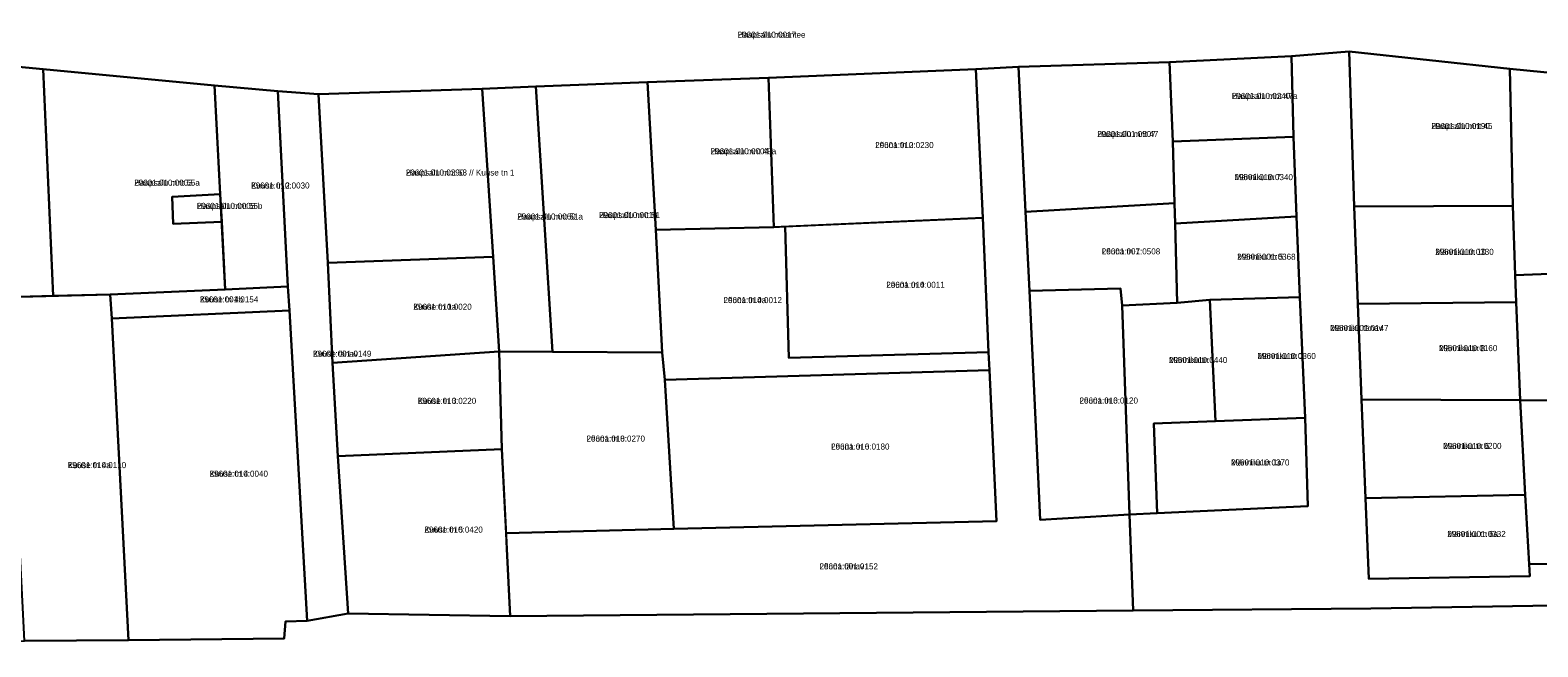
# Model space of a CAD drawing. Extents: x 518839 to 525192, y 6573164 to 6576561.
# Drawn here: x 522991.1 to 523365.3, y 6574299.5 to 6574452.7 of the extents above; entities that cross this region are included whole.
import ezdxf

# ---------------------------------------------------------------- set-up
doc = ezdxf.new("R2010")
doc.units = 0
for name, color, linetype in [('L_AADRESS', 7, 'Continuous'), ('PIIR', 7, 'Continuous'), ('TUNNUS', 7, 'Continuous')]:
    doc.layers.add(name, color=color, linetype=linetype)

msp = doc.modelspace()

# ---------------------------------------------------------------- linework, layer by layer
at = {"layer": 'PIIR'}
for points in [[(523375.25, 6574441.47), (523358.38, 6574443.13), (523318.49, 6574447.43), (523304.19, 6574446.22), (523273.88, 6574444.71), (523236.44, 6574443.56), (523225.85, 6574443.01), (523174.31, 6574440.89), (523144.32, 6574439.75), (523116.58, 6574438.68), (523103.26, 6574438.16), (523062.66, 6574436.81), (523052.55, 6574437.56), (523036.83, 6574438.96), (522994.3, 6574443.04), (522954.98, 6574446.76), (522904.74, 6574450.97), (522839.77, 6574456.33), (522694.1, 6574453.03)], [(522817.9, 6574265.68), (522818.87, 6574305.73), (522845.06, 6574303.47), (522909.55, 6574299.99), (522989.61, 6574301.01), (523015.47, 6574301.19), (523054.1, 6574301.61), (523054.47, 6574305.84), (523059.82, 6574306.01), (523069.97, 6574307.81), (523110.19, 6574307.2), (523264.85, 6574308.54), (523323.9, 6574309.05), (523389.23, 6574310.15)]]:
    msp.add_lwpolyline(points, dxfattribs=at)
for points in [[(522994.3, 6574443.04), (522996.8, 6574386.69), (522985.33, 6574386.41), (522958.36, 6574385.9), (522954.98, 6574446.76)], [(523304.72, 6574426.21), (523304.19, 6574446.22), (523318.49, 6574447.43), (523319.75, 6574408.88), (523320.68, 6574384.72), (523321.56, 6574360.96), (523322.56, 6574336.43), (523323.36, 6574316.4), (523363.35, 6574317.07), (523363.18, 6574320.07), (523388.79, 6574320.15), (523389.23, 6574310.15), (523323.9, 6574309.05), (523264.85, 6574308.54), (523264.01, 6574332.43), (523270.83, 6574332.75), (523308.28, 6574334.49), (523307.58, 6574356.42), (523306.24, 6574386.39), (523305.44, 6574406.38)], [(523273.88, 6574444.71), (523304.19, 6574446.22), (523304.72, 6574426.21), (523274.71, 6574425.02)], [(523359.17, 6574409.07), (523319.75, 6574408.88), (523318.49, 6574447.43), (523358.38, 6574443.13)], [(523036.83, 6574438.96), (523038.25, 6574411.98), (523026.31, 6574411.27), (523026.54, 6574404.64), (523038.61, 6574405.09), (523039.49, 6574388.26), (523010.94, 6574387.03), (522996.8, 6574386.69), (522994.3, 6574443.04)], [(523110.19, 6574307.2), (523109.38, 6574323.85), (523109.19, 6574327.74), (523150.83, 6574328.84), (523230.97, 6574330.77), (523229.19, 6574368.25), (523228.99, 6574372.75), (523227.53, 6574406.12), (523225.85, 6574443.01), (523236.44, 6574443.56), (523238.18, 6574407.6), (523239.13, 6574387.94), (523241.79, 6574331.1), (523264.01, 6574332.43), (523264.85, 6574308.54)], [(523174.31, 6574440.89), (523225.85, 6574443.01), (523227.53, 6574406.12), (523175.64, 6574403.81)], [(523238.18, 6574407.6), (523236.44, 6574443.56), (523273.88, 6574444.71), (523274.71, 6574425.02), (523275.14, 6574409.72)], [(523375.25, 6574441.47), (523374.88, 6574392.44), (523359.74, 6574391.88), (523359.17, 6574409.07), (523358.38, 6574443.13)], [(523399.43, 6574438.95), (523399.48, 6574434.63), (523400.69, 6574412.15), (523384.94, 6574411.42), (523386.45, 6574373.96), (523387.04, 6574360.55), (523360.93, 6574360.82), (523359.96, 6574385.13), (523359.74, 6574391.88), (523374.88, 6574392.44), (523375.25, 6574441.47)], [(523036.83, 6574438.96), (523052.55, 6574437.56), (523055.01, 6574389.05), (523039.49, 6574388.26)], [(523055.01, 6574389.05), (523052.55, 6574437.56), (523062.66, 6574436.81), (523064.93, 6574394.94), (523066.13, 6574370.09), (523067.45, 6574346.92), (523069.97, 6574307.81), (523059.82, 6574306.01), (523055.46, 6574383.09)], [(523062.66, 6574436.81), (523103.26, 6574438.16), (523105.98, 6574396.43), (523064.93, 6574394.94)], [(523105.98, 6574396.43), (523103.26, 6574438.16), (523116.58, 6574438.68), (523120.72, 6574372.82), (523107.52, 6574372.86)], [(523116.58, 6574438.68), (523144.32, 6574439.75), (523146.4, 6574403.12), (523147.99, 6574372.67), (523120.72, 6574372.82)], [(523174.31, 6574440.89), (523175.64, 6574403.81), (523146.4, 6574403.12), (523144.32, 6574439.75)], [(523275.28, 6574404.69), (523275.14, 6574409.72), (523274.71, 6574425.02), (523304.72, 6574426.21), (523305.44, 6574406.38)], [(523038.25, 6574411.98), (523038.61, 6574405.09), (523026.54, 6574404.64), (523026.31, 6574411.27)], [(523239.13, 6574387.94), (523238.18, 6574407.6), (523275.14, 6574409.72), (523275.28, 6574404.69), (523275.84, 6574384.99), (523262.14, 6574384.3), (523261.74, 6574388.5)], [(523320.68, 6574384.72), (523319.75, 6574408.88), (523359.17, 6574409.07), (523359.74, 6574391.88), (523359.96, 6574385.13)], [(523146.4, 6574403.12), (523175.64, 6574403.81), (523178.47, 6574403.94), (523179.43, 6574371.29), (523228.99, 6574372.75), (523229.19, 6574368.25), (523148.62, 6574365.88), (523147.99, 6574372.67)], [(523178.47, 6574403.94), (523227.53, 6574406.12), (523228.99, 6574372.75), (523179.43, 6574371.29)], [(523283.89, 6574385.71), (523275.84, 6574384.99), (523275.28, 6574404.69), (523305.44, 6574406.38), (523306.24, 6574386.39)], [(523064.93, 6574394.94), (523105.98, 6574396.43), (523107.52, 6574372.86), (523066.13, 6574370.09)], [(523011.36, 6574381.1), (523010.94, 6574387.03), (523039.49, 6574388.26), (523055.01, 6574389.05), (523055.46, 6574383.09)], [(522985.33, 6574386.41), (523010.94, 6574387.03), (523011.36, 6574381.1), (523015.47, 6574301.19), (522989.61, 6574301.01)], [(523239.13, 6574387.94), (523261.74, 6574388.5), (523262.14, 6574384.3), (523264.01, 6574332.43), (523241.79, 6574331.1)], [(523275.84, 6574384.99), (523283.89, 6574385.71), (523285.36, 6574355.61), (523269.99, 6574355.04), (523270.83, 6574332.75), (523264.01, 6574332.43), (523262.14, 6574384.3)], [(523285.36, 6574355.61), (523283.89, 6574385.71), (523306.24, 6574386.39), (523307.58, 6574356.42)], [(523320.68, 6574384.72), (523359.96, 6574385.13), (523360.93, 6574360.82), (523321.56, 6574360.96)], [(523011.36, 6574381.1), (523055.46, 6574383.09), (523059.82, 6574306.01), (523054.47, 6574305.84), (523054.1, 6574301.61), (523015.47, 6574301.19)], [(523066.13, 6574370.09), (523107.52, 6574372.86), (523108.16, 6574348.64), (523067.45, 6574346.92)], [(523148.62, 6574365.88), (523150.83, 6574328.84), (523109.19, 6574327.74), (523108.16, 6574348.64), (523107.52, 6574372.86), (523120.72, 6574372.82), (523147.99, 6574372.67)], [(523148.62, 6574365.88), (523229.19, 6574368.25), (523230.97, 6574330.77), (523150.83, 6574328.84)], [(523321.56, 6574360.96), (523360.93, 6574360.82), (523362.23, 6574337.28), (523322.56, 6574336.43)], [(523362.23, 6574337.28), (523360.93, 6574360.82), (523387.04, 6574360.55), (523388.79, 6574320.15), (523363.18, 6574320.07)], [(523270.83, 6574332.75), (523269.99, 6574355.04), (523285.36, 6574355.61), (523307.58, 6574356.42), (523308.28, 6574334.49)], [(523108.16, 6574348.64), (523109.38, 6574323.85), (523110.19, 6574307.2), (523069.97, 6574307.81), (523067.45, 6574346.92)], [(523322.56, 6574336.43), (523362.23, 6574337.28), (523363.18, 6574320.07), (523363.35, 6574317.07), (523323.36, 6574316.4)]]:
    msp.add_lwpolyline(points, close=True, dxfattribs=at)

# ---------------------------------------------------------------- texts
at = {"layer": 'L_AADRESS'}
for s, p in [('Haapsalu maantee', (523166.69, 6574450.83)), ('Haapsalu mnt 47a', (523289.37, 6574435.62)), ('Haapsalu mnt 47', (523255.97, 6574426.16)), ('Haapsalu mnt 45', (523338.92, 6574428.15)), ('Haapsalu mnt 49a', (523159.98, 6574421.89)), ('Lõuna tn 2', (523200.84, 6574423.41)), ('Haapsalu mnt 55a', (523016.89, 6574414.08)), ('Haapsalu mnt 53 // Kuuse tn 1', (523084.32, 6574416.59)), ('Männiku tn 7', (523290.04, 6574415.45)), ('Kuuse tn 2', (523045.92, 6574413.37)), ('Haapsalu mnt 55b', (523032.43, 6574408.31)), ('Haapsalu mnt 51', (523132.29, 6574406.02)), ('Haapsalu mnt 51a', (523111.99, 6574405.67)), ('Lõuna tn 7', (523257.1, 6574397.01)), ('Männiku tn 5', (523290.7, 6574395.68)), ('Männiku tn 10', (523339.89, 6574396.9)), ('Lõuna tn 4', (523203.6, 6574388.71)), ('Kuuse tn 4b', (523033.19, 6574385.08)), ('Lõuna tn 4a', (523163.19, 6574384.91)), ('Kuuse tn 1a', (523086.17, 6574383.26)), ('Männiku tänav', (523313.77, 6574377.99)), ('Männiku tn 8', (523340.78, 6574372.98)), ('Kuuse tänav', (523061.26, 6574371.59)), ('Männiku tn 1', (523273.75, 6574370.03)), ('Männiku tn 3', (523295.73, 6574371.03)), ('Kuuse tn 3', (523087.29, 6574359.89)), ('Lõuna tn 5', (523251.57, 6574359.97)), ('Lõuna tn 8', (523129.18, 6574350.52)), ('Lõuna tn 6', (523189.89, 6574348.54)), ('Männiku tn 6', (523341.83, 6574348.7)), ('Kuuse tn 4a', (523000.4, 6574343.93)), ('Männiku tn 1a', (523289.17, 6574344.59)), ('Kuuse tn 4', (523035.59, 6574341.8)), ('Kuuse tn 5', (523088.93, 6574327.92)), ('Männiku tn 6a', (523342.87, 6574326.84)), ('Lõuna tänav', (523187.02, 6574318.79))]:
    msp.add_text(s, height=1.5, dxfattribs=at).set_placement(p)
at = {"layer": 'TUNNUS'}
for s, p in [('29601:010:0017', (523166.69, 6574450.83)), ('29601:010:0240', (523289.37, 6574435.62)), ('29601:001:0507', (523255.97, 6574426.16)), ('29601:010:0190', (523338.92, 6574428.15)), ('29601:010:0004', (523159.98, 6574421.89)), ('29601:010:0230', (523200.84, 6574423.41)), ('29601:010:0003', (523016.89, 6574414.08)), ('29601:010:0290', (523084.32, 6574416.59)), ('29601:010:0340', (523290.04, 6574415.45)), ('29601:010:0030', (523045.92, 6574413.37)), ('29601:010:0005', (523032.43, 6574408.31)), ('29601:010:0060', (523111.99, 6574405.67)), ('29601:010:0010', (523132.29, 6574406.02)), ('29601:001:0508', (523257.1, 6574397.01)), ('29601:001:0368', (523290.7, 6574395.68)), ('29601:010:0330', (523339.89, 6574396.9)), ('29601:010:0011', (523203.6, 6574388.71)), ('29601:001:0154', (523033.19, 6574385.08)), ('29601:010:0012', (523163.19, 6574384.91)), ('29601:010:0020', (523086.17, 6574383.26)), ('29601:001:0147', (523313.77, 6574377.99)), ('29601:010:0160', (523340.78, 6574372.98)), ('29601:001:0149', (523061.26, 6574371.59)), ('29601:010:0440', (523273.75, 6574370.03)), ('29601:010:0360', (523295.73, 6574371.03)), ('29601:010:0220', (523087.29, 6574359.89)), ('29601:010:0120', (523251.57, 6574359.97)), ('29601:010:0270', (523129.18, 6574350.52)), ('29601:010:0180', (523189.89, 6574348.54)), ('29601:010:0200', (523341.83, 6574348.7)), ('29601:010:0110', (523000.4, 6574343.93)), ('29601:010:0370', (523289.17, 6574344.59)), ('29601:010:0040', (523035.59, 6574341.8)), ('29601:010:0420', (523088.93, 6574327.92)), ('29601:001:0332', (523342.87, 6574326.84)), ('29601:001:0152', (523187.02, 6574318.79))]:
    msp.add_text(s, height=1.5, dxfattribs=at).set_placement(p)

doc.saveas('drawing.dxf')
